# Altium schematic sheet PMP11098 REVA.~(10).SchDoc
size 431 x 279 mm; Date: Not shown in title block; ApprovedBy: Not shown in title block; CheckedBy: Not shown in title block; Author: Not shown in title block; CompanyName: Not shown in title block; Engineer: Not shown in title block; Organization: Not shown in title block; Address1: Not shown in title block; Address2: Not shown in title block; Address3: Not shown in title block; Address4: Not shown in title block; DocumentNumber: 1; Revision: Use project parameter SCH_Rev; SheetNumber: 1; SheetTotal: 1; PageSetup: Record=PageOptions¦CenterHorizontal=True¦CenterVertical=True¦PrintScale=1.00¦XCorrection=1.00¦YCorrection=1.00¦PrintKind=0¦BorderSize=5000000¦LeftOffset=0¦BottomOffset=0¦Orientation=2¦PaperLength=1000¦PaperWidth=1000¦Scale=100¦PaperSource=15¦PrintQuality=600¦MediaType=1¦DitherType=10¦PaperKind=Letter¦PrintScaleMode=1
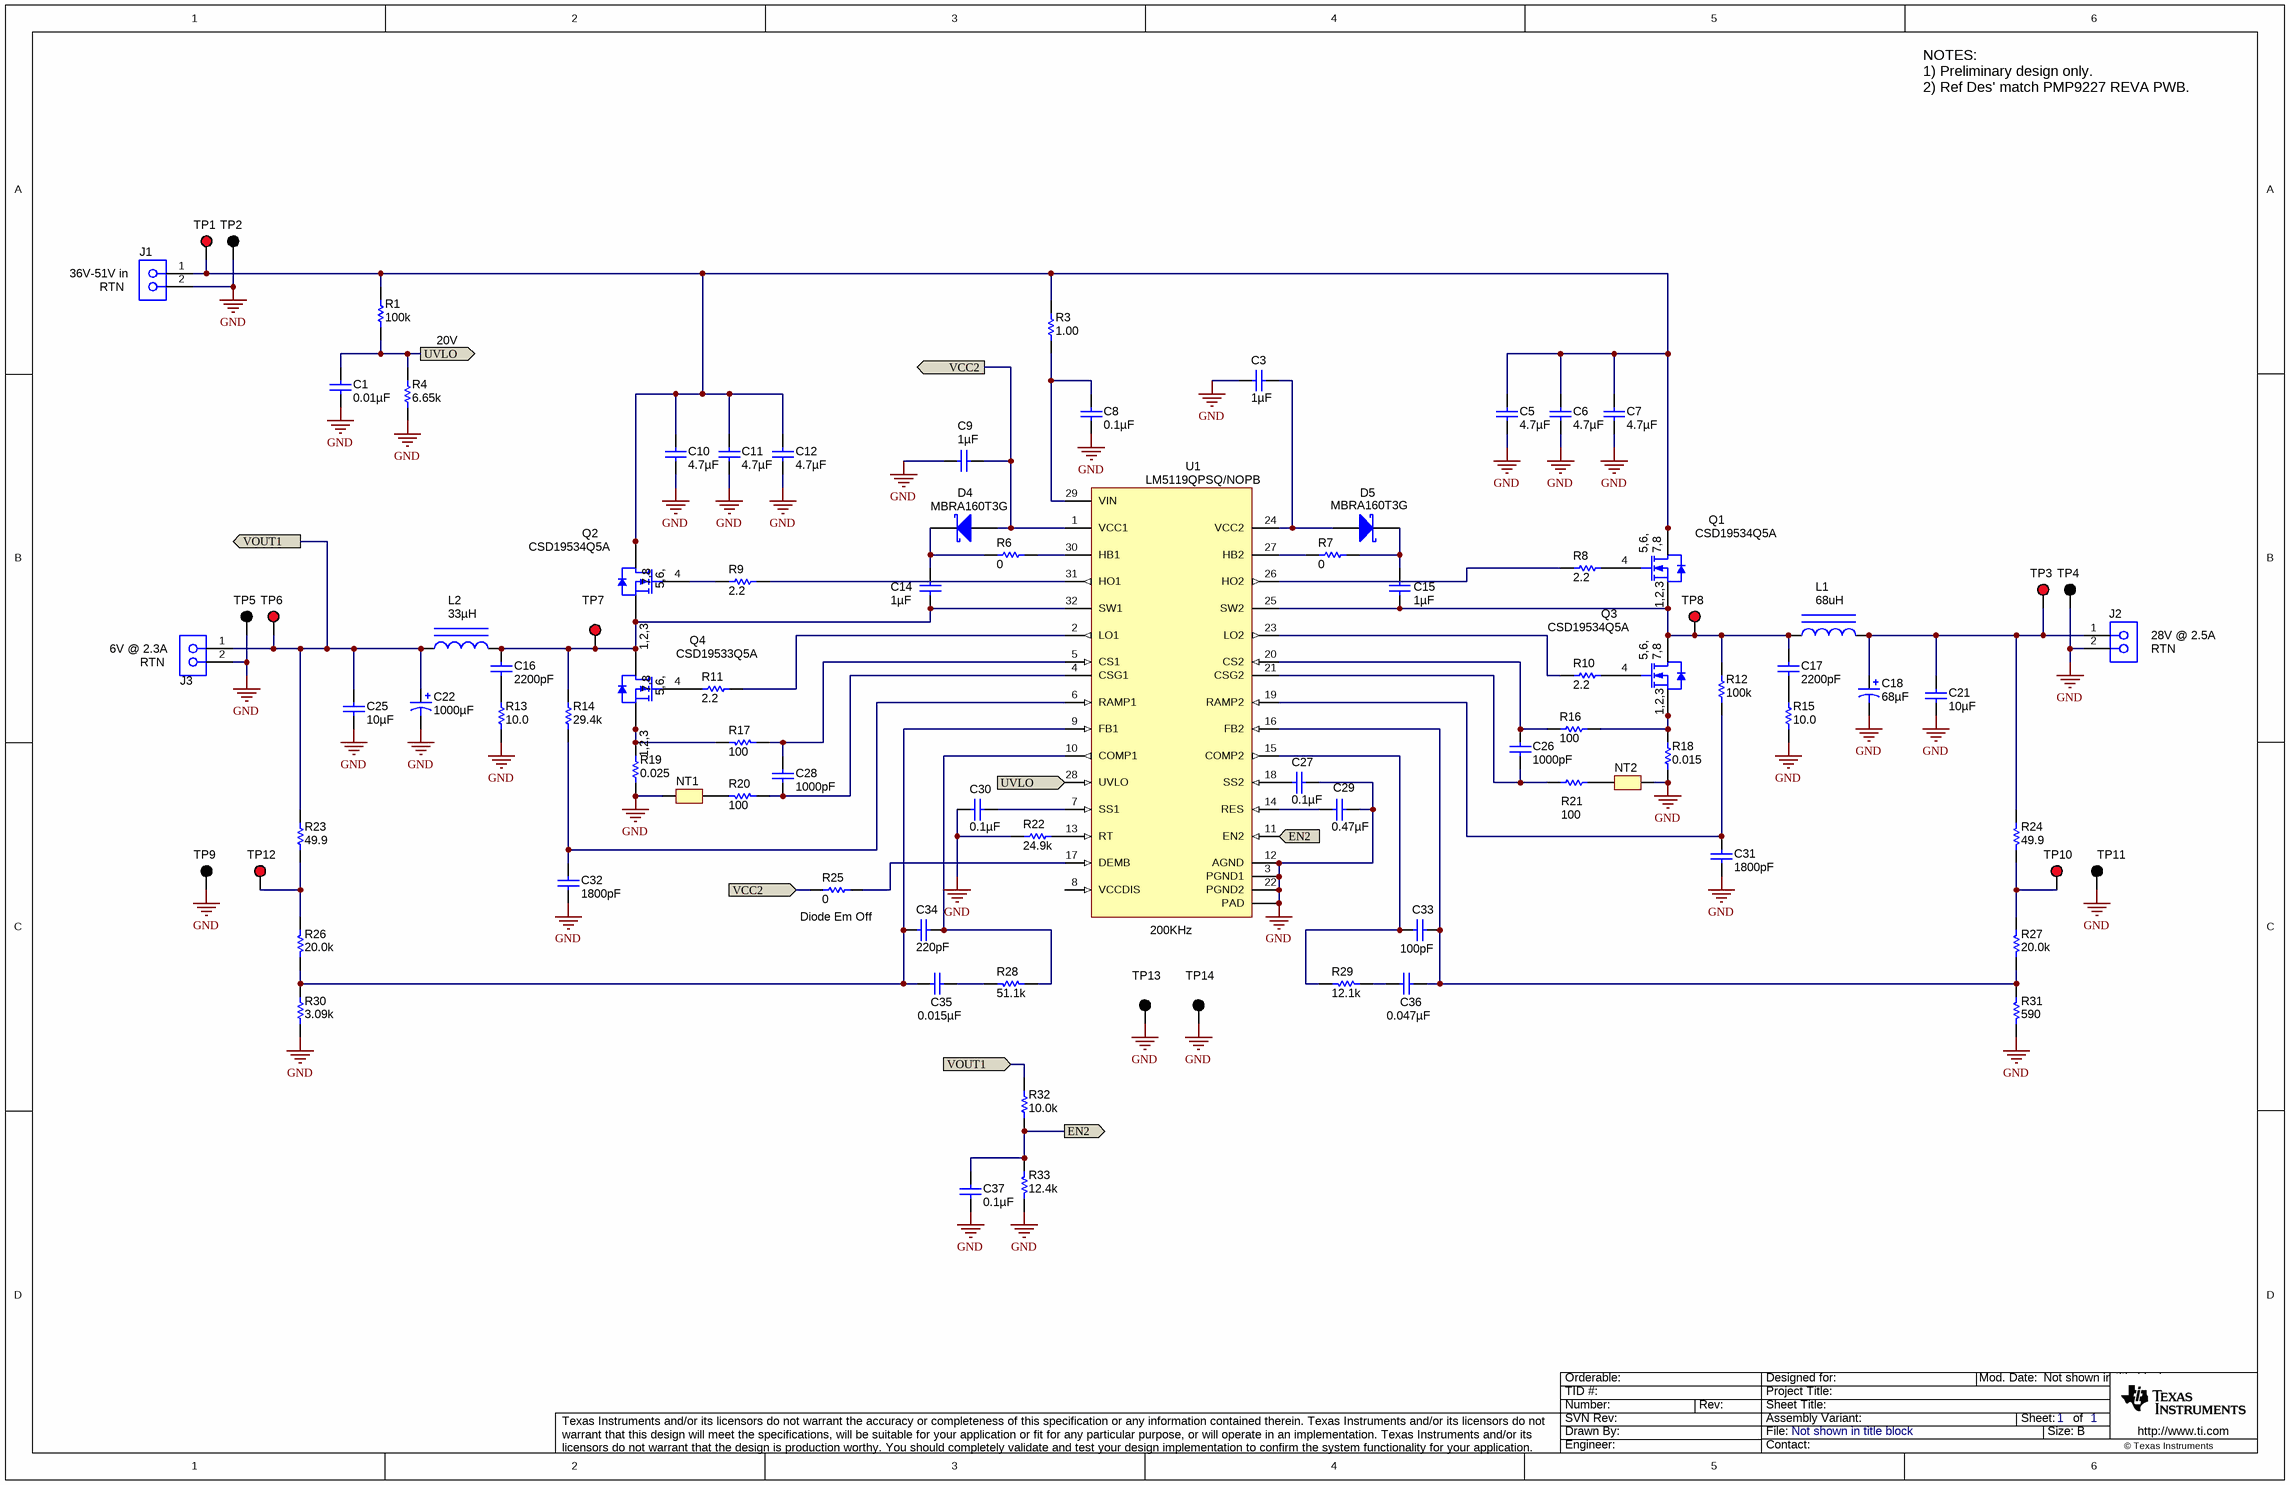
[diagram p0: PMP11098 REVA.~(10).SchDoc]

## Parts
C1  ValueDisplayed: 0.01µF  [0603L]  (hidden comment: C1608X7R1H103K)
C3  ValueDisplayed: 1µF  [0603L]  (hidden comment: C1608X7R1E105K080AB)
C5  ValueDisplayed: 4.7µF  [1210L]  (hidden comment: C3225X7S2A475M200AB)
C6  ValueDisplayed: 4.7µF  [1210L]  (hidden comment: C3225X7S2A475M200AB)
C7  ValueDisplayed: 4.7µF  [1210L]  (hidden comment: C3225X7S2A475M200AB)
C8  ValueDisplayed: 0.1µF  [0603L]  (hidden comment: 06035C104KAT2A)
C9  ValueDisplayed: 1µF  [0603L]  (hidden comment: C1608X7R1E105K080AB)
C10  ValueDisplayed: 4.7µF  [1210L]  (hidden comment: C3225X7S2A475M200AB)
C11  ValueDisplayed: 4.7µF  [1210L]  (hidden comment: C3225X7S2A475M200AB)
C12  ValueDisplayed: 4.7µF  [1210L]  (hidden comment: C3225X7S2A475M200AB)
C14  ValueDisplayed: 1µF  [0603L]  (hidden comment: C1608X7R1E105K080AB)
C15  ValueDisplayed: 1µF  [0603L]  (hidden comment: C1608X7R1E105K080AB)
C16  ValueDisplayed: 2200pF  [0603L]  (hidden comment: C0603C222K5RAC)
C17  ValueDisplayed: 2200pF  [0603L]  (hidden comment: C0603C222K5RAC)
C18  ValueDisplayed: 68µF  [SM_RADIAL_10AMM]  (hidden comment: 50SVPF68M)
C21  ValueDisplayed: 10µF  [1210L]  (hidden comment: GMK325AB7106MM-T)
C22  ValueDisplayed: 1000µF  [SM_RADIAL_10AMM]  (hidden comment: 16SVPF1000M)
C25  ValueDisplayed: 10µF  [1210L]  (hidden comment: GMK325AB7106MM-T)
C26  ValueDisplayed: 1000pF  [0603L]  (hidden comment: 06031C102KAT2A)
C27  ValueDisplayed: 0.1µF  [0603L]  (hidden comment: C1608X7R1H104K)
C28  ValueDisplayed: 1000pF  [0603L]  (hidden comment: 06031C102KAT2A)
C29  ValueDisplayed: 0.47µF  [0603L]  (hidden comment: C0603C474K4RACTU)
C30  ValueDisplayed: 0.1µF  [0603L]  (hidden comment: C1608X7R1H104K)
C31  ValueDisplayed: 1800pF  [0603L]  (hidden comment: C1608C0G1H182J)
C32  ValueDisplayed: 1800pF  [0603L]  (hidden comment: C1608C0G1H182J)
C33  ValueDisplayed: 100pF  [0603]  (hidden comment: C1608C0G1H101J)
C34  ValueDisplayed: 220pF  [0603]  (hidden comment: C1608C0G1H221J)
C35  ValueDisplayed: 0.015µF  [0603L]  (hidden comment: C1608X7R1H153K)
C36  ValueDisplayed: 0.047µF  [0603]  (hidden comment: C1608X7R1H473K)
C37  ValueDisplayed: 0.1µF  [0603L]  (hidden comment: C1608X7R1H104K)
D4  MBRA160T3G  [SMA]
D5  MBRA160T3G  [SMA]
J1  ED120/2DS  [CONN_ED120-2DS]  (value not drawn)
J2  ED120/2DS  [CONN_ED120-2DS]  (value not drawn)
J3  ED120/2DS  [CONN_ED120-2DS]  (value not drawn)
L1  value 68uH  [MSS1210]  (hidden comment: MSS1210-683ME)
L2  ValueDisplayed: 33µH  [MSS1210]  (hidden comment: MSS1210-333ME)
NT1  Net-Tie  [Net-Tie_10mil]  (value not drawn)  (net tie, no BOM)
NT2  Net-Tie  [Net-Tie_10mil]  (value not drawn)  (net tie, no BOM)
Q1  CSD19534Q5A  [TRANS_NexFET_Q5A]
Q2  CSD19534Q5A  [TRANS_NexFET_Q5A]
Q3  CSD19534Q5A  [TRANS_NexFET_Q5A]
Q4  CSD19533Q5A  [TRANS_NexFET_Q5A]
R1  value 100k  [0603L]  (hidden comment: CRCW0603100KFKEA)
R3  value 1.00  [0603L]  (hidden comment: CRCW06031R00FKEA)
R4  value 6.65k  [0603L]  (hidden comment: CRCW06036K65FKEA)
R6  value 0  [0603L]  (hidden comment: CRCW06030000Z0EA)
R7  value 0  [0603L]  (hidden comment: CRCW06030000Z0EA)
R8  value 2.2  [0603L]  (hidden comment: CRCW06032R20JNEA)
R9  value 2.2  [0603L]  (hidden comment: CRCW06032R20JNEA)
R10  value 2.2  [0603L]  (hidden comment: CRCW06032R20JNEA)
R11  value 2.2  [0603L]  (hidden comment: CRCW06032R20JNEA)
R12  ValueDisplayed: 100k  [0603]  (hidden comment: CRCW0603100KFKEA)
R13  value 10.0  [1206L]  (hidden comment: CRCW120610R0FKEA)
R14  ValueDisplayed: 29.4k  [0603]  (hidden comment: CRCW060329K4FKEA)
R15  value 10.0  [1206L]  (hidden comment: CRCW120610R0FKEA)
R16  value 100  [0603L]  (hidden comment: RC0603FR-07100RL)
R17  value 100  [0603L]  (hidden comment: RC0603FR-07100RL)
R18  value 0.015  [1206]  (hidden comment: CSR1206FK15L0)
R19  ValueDisplayed: 0.025  [2010]  (hidden comment: CSRN2010FK25L0)
R20  value 100  [0603L]  (hidden comment: RC0603FR-07100RL)
R21  value 100  [0603L]  (hidden comment: RC0603FR-07100RL)
R22  ValueDisplayed: 24.9k  [0603L]  (hidden comment: CRCW060324K9FKEA)
R23  value 49.9  [0603L]  (hidden comment: CRCW060349R9FKEA)
R24  value 49.9  [0603L]  (hidden comment: CRCW060349R9FKEA)
R25  value 0  [0603L]  (hidden comment: CRCW06030000Z0EA)
R26  value 20.0k  [0603L]  (hidden comment: CRCW060320K0FKEA)
R27  value 20.0k  [0603L]  (hidden comment: CRCW060320K0FKEA)
R28  value 51.1k  [0603]  (hidden comment: CRCW060351K1FKEA)
R29  ValueDisplayed: 12.1k  [0603]  (hidden comment: CRCW060312K1FKEA)
R30  ValueDisplayed: 3.09k  [0603L]  (hidden comment: CRCW06033K09FKEA)
R31  ValueDisplayed: 590  [0603]  (hidden comment: CRCW0603590RFKEA)
R32  value 10.0k  [0603L]  (hidden comment: CRCW060310K0FKEA)
R33  value 12.4k  [0603]  (hidden comment: CRCW060312K4FKEA)
TP1  5010  [Keystone5010]  (value not drawn)
TP2  5011  [Keystone5011]  (value not drawn)
TP3  5010  [Keystone5010]  (value not drawn)
TP4  5011  [Keystone5011]  (value not drawn)
TP5  5011  [Keystone5011]  (value not drawn)
TP6  5010  [Keystone5010]  (value not drawn)
TP7  5010  [Keystone5010]  (value not drawn)
TP8  5010  [Keystone5010]  (value not drawn)
TP9  5011  [Keystone5011]  (value not drawn)
TP10  5010  [Keystone5010]  (value not drawn)
TP11  5011  [Keystone5011]  (value not drawn)
TP12  5010  [Keystone5010]  (value not drawn)
TP13  5011  [Keystone5011]  (value not drawn)
TP14  5011  [Keystone5011]  (value not drawn)
U1  LM5119QPSQ/NOPB  [RTV0032A]

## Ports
EN2, UVLO, VCC2, VOUT1

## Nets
GND: C1.2 C3.2 C5.2 C6.2 C7.2 C8.2 C9.2 C10.2 C11.2 C12.2 C18.2(-) C21.2 C22.2(-) C25.2 C27.1 C29.1 C30.2 C31.2 C32.2 C37.2 J1.2 J2.2 J3.2 NT1.1 NT2.2 R4.1 R13.1 R15.1 R18.1 R19.1 R22.1 R30.1 R31.1 R33.1 TP2.1 TP4.1 TP5.1 TP9.1 TP11.1 TP13.1 TP14.1 U1.3(PGND1) U1.12(AGND) U1.22(PGND2) U1.33(PAD)
EN2: C37.1 R32.1 R33.2 U1.11(EN2) ; port EN2
UVLO: C1.1 R1.1 R4.2 U1.28(UVLO) ; port UVLO
VCC2: C9.1 D4.2(A) R25.1 U1.1(VCC1) ; port VCC2
VOUT1: C22.1(+) C25.1 J3.1 L2.1 R23.2 R32.2 TP6.1 ; port VOUT1
NetC3_1: C3.1 D5.2(A) U1.24(VCC2)
NetC5_1: C5.1 C6.1 C7.1 C10.1 C11.1 C12.1 J1.1 Q1.5(D) Q1.6(D) Q1.7(D) Q1.8(D) Q1.9(D) Q2.5(D) Q2.6(D) Q2.7(D) Q2.8(D) Q2.9(D) R1.2 R3.2 TP1.1
NetC8_1: C8.1 R3.1 U1.29(VIN)
NetC14_1: C14.1 D4.1(K) R6.1
NetC14_2: C14.2 C16.1 L2.2 Q2.1(S) Q2.2(S) Q2.3(S) Q4.5(D) Q4.6(D) Q4.7(D) Q4.8(D) Q4.9(D) R14.2 TP7.1 U1.32(SW1)
NetC15_1: C15.1 D5.1(K) R7.2
NetC15_2: C15.2 C17.1 L1.1 Q1.1(S) Q1.2(S) Q1.3(S) Q3.5(D) Q3.6(D) Q3.7(D) Q3.8(D) Q3.9(D) R12.2 TP8.1 U1.25(SW2)
NetC16_2: C16.2 R13.2
NetC17_2: C17.2 R15.2
NetC18_1: C18.1(+) C21.1 J2.1 L1.2 R24.2 TP3.1
NetC26_1: C26.1 R21.1 U1.21(CSG2)
NetC26_2: C26.2 R16.1 U1.20(CS2)
NetC27_2: C27.2 U1.18(SS2)
NetC28_1: C28.1 R17.1 U1.5(CS1)
NetC28_2: C28.2 R20.1 U1.4(CSG1)
NetC29_2: C29.2 U1.14(RES)
NetC30_1: C30.1 U1.7(SS1)
NetC31_1: C31.1 R12.1 U1.19(RAMP2)
NetC32_1: C32.1 R14.1 U1.6(RAMP1)
NetC33_1: C33.1 C36.1 R27.1 R31.2 U1.16(FB2)
NetC33_2: C33.2 R29.2 U1.15(COMP2)
NetC34_1: C34.1 R28.1 U1.10(COMP1)
NetC34_2: C34.2 C35.2 R26.1 R30.2 U1.9(FB1)
NetC35_1: C35.1 R28.2
NetC36_2: C36.2 R29.1
NetNT1_2: NT1.2 R20.2
NetNT2_1: NT2.1 R21.2
NetQ1_4: Q1.4(G) R8.2
NetQ2_4: Q2.4(G) R9.1
NetQ3_1: Q3.1(S) Q3.2(S) Q3.3(S) R16.2 R18.2
NetQ3_4: Q3.4(G) R10.2
NetQ4_1: Q4.1(S) Q4.2(S) Q4.3(S) R17.2 R19.2
NetQ4_4: Q4.4(G) R11.1
NetR6_2: R6.2 U1.30(HB1)
NetR7_1: R7.1 U1.27(HB2)
NetR8_1: R8.1 U1.26(HO2)
NetR9_2: R9.2 U1.31(HO1)
NetR10_1: R10.1 U1.23(LO2)
NetR11_2: R11.2 U1.2(LO1)
NetR22_2: R22.2 U1.13(RT)
NetR23_1: R23.1 R26.2 TP12.1
NetR24_1: R24.1 R27.2 TP10.1
NetR25_2: R25.2 U1.17(DEMB)

Not connected (* = marked no-connect by the designer): U1 8(VCCDIS)

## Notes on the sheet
- NOTES:
  1) Preliminary design only.
  2) Ref Des' match PMP9227 REVA PWB.
- (near J1) 36V-51V in
- (near J1) RTN
- 20V
- (near J2) 28V @ 2.5A
- (near J3) 6V @ 2.3A
- (near J3) RTN
- (near J2) RTN
- (near R25) Diode Em Off
- (near U1) 200KHz

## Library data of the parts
C1 = C1608X7R1H103K: CAP, CERM, 0.01uF, 50V, +/-10%, X7R, 0603; Manufacturer: TDK; Polarized: N; CompType: Capacitor; U/M: EA; Cap_F: 0.00000001; Tolerance_%: 10; ESR_Ohm: 0.0539; Value1: 0.0539 ohm; VDC_V: 50; TaMin_C: -55; TaMax_C: 125; Cap_Case: 0603
C3 C9 C14 C15 = C1608X7R1E105K080AB: CAP, CERM, 1uF, 25V, +/-10%, X7R, 0603; Manufacturer: TDK; Polarized: N; CompType: Capacitor; U/M: EA; Cap_F: 0.000001; Tolerance_%: 10; Value1: Unknown; VDC_V: 25; TaMin_C: -55; TaMax_C: 125; Cap_Case: 0603
C5-C7 C10-C12 = C3225X7R1H335M: CAP, CERM, 4.7uF, 100V, +/-20%, X7S, 1210; Manufacturer: TDK; Polarized: N; CompType: Capacitor; U/M: EA; Cap_F: 0.0000033; Tolerance_%: 20; Value1: Unknown; VDC_V: 100; TempCo: X7R; TaMin_C: -55; TaMax_C: 125; Cap_Case: 1210
C8 = 06035C104KAT2A: CAP, CERM, 0.1uF, 50V, +/-10%, X7R, 0603; Manufacturer: AVX; Polarized: N; CompType: Capacitor; U/M: EA; Cap_F: 0.0000001; Tolerance_%: 10; Value1: Unknown; VDC_V: 50; TaMin_C: -55; TaMax_C: 125; Cap_Case: 0603
C16 C17 = C0603C222K5RAC: CAP, CERM, 2200pF, 50V, +/-10%, X7R, 0603; Manufacturer: Kemet; Polarized: N; CompType: Capacitor; U/M: EA; Cap_F: 0.0000000022; Tolerance_%: 10; Value1: Unknown; VDC_V: 50; TaMin_C: -55; TaMax_C: 125; Cap_Case: 0603
C18 = 10SVP270M: CAP, OS-CON, 68uF, 50V, +/-20%, 0.020 ohm, F12, SMD; Manufacturer: Sanyo; Polarized: Y; CompType: Capacitor; U/M: EA; Cap_F: 0.00027; Tolerance_%: 20; VDC_V: 50; ESR_Ohm: 0.025; IRMS_A: 3.7; TaMin_C: -55; TaMax_C: 105; Cap_Case: 10.3x10.3x7.9
C21 C25 = GMK325AB7106MM-T: CAP, CERM, 10uF, 35V, +/-20%, X7R, 1210; Manufacturer: Taiyo Yuden; Polarized: N; CompType: Capacitor; U/M: EA; Cap_F: 0.00001; Tolerance_%: 20; Value1: Unknown; VDC_V: 35; TaMin_C: -55; TaMax_C: 125; Cap_Case: 1210
C22 = 10SVP270M: CAP, OS-CON, 1000uF, 16V, +/-20%, 0.012 ohm, F12, SMD; Manufacturer: Sanyo; Polarized: Y; CompType: Capacitor; U/M: EA; Cap_F: 0.00027; Tolerance_%: 20; VDC_V: 16; ESR_Ohm: 0.025; IRMS_A: 3.7; TaMin_C: -55; TaMax_C: 105; Cap_Case: 10.3x10.3x7.9
C26 C28 = 06031C102KAT2A: CAP, CERM, 1000pF, 100V, +/-10%, X7R, 0603; Manufacturer: AVX; Polarized: N; CompType: Capacitor; U/M: EA; Cap_F: 0.000000001; Tolerance_%: 10; ESR_Ohm: 0.276; Value1: 0.276 ohm; VDC_V: 100; TaMin_C: -55; TaMax_C: 125; Cap_Case: 0603
C27 C30 C37 = C1608X7R1H104K: CAP, CERM, 0.1uF, 50V, +/-10%, X7R, 0603; Manufacturer: TDK; Polarized: N; CompType: Capacitor; U/M: EA; Cap_F: 0.0000001; Tolerance_%: 10; ESR_Ohm: 0.017; Value1: 0.017 ohm; VDC_V: 50; TaMin_C: -55; TaMax_C: 125; Cap_Case: 0603
C29 = C0603C474K4RACTU: CAP, CERM, 0.47uF, 16V, +/-10%, X7R, 0603; Manufacturer: Kemet; Polarized: N; CompType: Capacitor; U/M: EA; Cap_F: 0.00000047; Tolerance_%: 10; Value1: Unknown; VDC_V: 16; TaMin_C: -55; TaMax_C: 125; Cap_Case: 0603
C31 C32 = C1608C0G1H182J: CAP, CERM, 1800pF, 50V, +/-5%, C0G/NP0, 0603; Manufacturer: TDK; Polarized: N; CompType: Capacitor; U/M: EA; Cap_F: 0.0000000018; Tolerance_%: 5; Value1: Unknown; VDC_V: 50; TaMin_C: -55; TaMax_C: 125; Cap_Case: 0603
C33 = C1608C0G1H101J: CAP, CERM, 100pF, 50V, +/-5%, C0G/NP0, 0603; Manufacturer: TDK; Polarized: N; CompType: Capacitor; U/M: EA; Cap_F: 0.0000000001; Tolerance_%: 5; ESR_Ohm: 0.1679; Value1: 0.1679 ohm; VDC_V: 50; TaMin_C: -55; TaMax_C: 125
C34 = C1608C0G1H221J: CAP, CERM, 220pF, 50V, +/-5%, C0G/NP0, 0603; Manufacturer: TDK; Polarized: N; CompType: Capacitor; U/M: EA; Cap_F: 0.00000000022; Tolerance_%: 5; ESR_Ohm: 0.0831; Value1: 0.0831 ohm; VDC_V: 50; TaMin_C: -55; TaMax_C: 125
C35 = C1608X7R1H473K: CAP, CERM, 0.015uF, 50V, +/-10%, X7R, 0603; Manufacturer: TDK; Polarized: N; CompType: Capacitor; U/M: EA; Cap_F: 0.000000047; Tolerance_%: 10; ESR_Ohm: 0.0234; Value1: 0.0234 ohm; VDC_V: 50; TaMin_C: -55; TaMax_C: 125; Cap_Case: 0603
C36 = C1608X7R1H473K: CAP, CERM, 0.047uF, 50V, +/-10%, X7R, 0603; Manufacturer: TDK; Polarized: N; CompType: Capacitor; U/M: EA; Cap_F: 0.000000047; Tolerance_%: 10; ESR_Ohm: 0.0234; Value1: 0.0234 ohm; VDC_V: 50; TaMin_C: -55; TaMax_C: 125
D4 D5 = MBRA160T3G: Diode, Schottky, 60V, 1A, SMA; Manufacturer: ON Semiconductor; Value: 0.51V; U/M: EA; Vf_V: 0.51; Io_A: 1; Vr_V: 60; TJmax_C: 150; RJC_CperW: 35
J1-J3 = ED120/2DS: TERMINAL BLOCK 5.08MM VERT 2POS; Manufacturer: On-Shore Technology, Inc.; U/M: EA
L1 = MSS1210-683ME: Inductor, Shielded, Ferrite, 68 µH, 4.3 A, 0.074 ohm, SMD; Manufacturer: Coilcraft; Ind_H: 68.0E-6; ValueDisplayed: 68µH; Imax_A: 4.3; Irms: 4.3A @ 40C rise; Isat: 4.9A @ 30% inductance drop; DCR_ohm: 0.074; Value2: 4.3A
L2 = MSS1210-333ME: Inductor, Shielded, Ferrite, 33 µH, 5.9 A, 0.034 ohm, SMD; Manufacturer: Coilcraft; Value: 33uH; Ind_H: 33.0E-6; Imax_A: 5.9; Irms: 5.9A @ 40C rise; Isat: 6.9A @ 30% inductance drop; DCR_ohm: 0.034; Value2: 5.9A
NT1 NT2 = Net-Tie: Single point connection between nets.; SymbolCreator: codlsc
Q1-Q3 = CSD19531Q5A: MOSFET, N-CH, 100V, 15nC, 0.0124 ohm, SON 5x6mm; Manufacturer: Texas Instruments; Alternate Manufacturer: None; U/M: EA; ChType: N; VdsMax_V: 100; QgTyp_nC: 26; Vgs_V: 20; IdsMax_A: 16
Q4 = CSD19533Q5A: MOSFET, N-CH, 100V, 13A, SON 5x6mm; Manufacturer: Texas Instruments; Alternate Manufacturer: None; U/M: EA; ChType: N; VdsMax_V: 100; Value1: ? ohm; Value2: 27 nC; QgTyp_nC: 27; Vgs_V: 20; IdsMax_A: 13
R1 = CRCW0603100KFKEA: RES, 100k ohm, 1%, 0.1W, 0603; Manufacturer: Vishay-Dale; CompType: Resistor; Res_ohm: 100000; Tolerance_%: 1; Power_W: 0.1; VDC_V: 75; TempCo: 100 ppm/C; EIA_Code: E96; U/M: EA
R3 = CRCW06031R00FKEA: RES, 1.00 ohm, 1%, 0.1W, 0603; Manufacturer: Vishay-Dale; CompType: Resistor; Res_ohm: 1; Value_Code: 1R00; Power_W: 0.1; VDC_V: 75; TempCo: 100 ppm/C; EIA_Code: E96; U/M: EA
R4 = CRCW06036K65FKEA: RES, 6.65k ohm, 1%, 0.1W, 0603; Manufacturer: Vishay-Dale; CompType: Resistor; Res_ohm: 6650; Value_Code: 6k65; Tolerance_%: 1; Power_W: 0.1; VDC_V: 75; TempCo: 100 ppm/C; EIA_Code: E96; U/M: EA
R6 R7 R25 = CRCW06030000Z0EA: RES, 0 ohm, 5%, 0.1W, 0603; Manufacturer: Vishay-Dale; CompType: Resistor; Value_Code: 0000; Tolerance_%: 5; Power_W: 0.1; VDC_V: 75; TempCo: 200 ppm/C; EIA_Code: E24; U/M: EA
R8-R11 = CRCW06032R20JNEA: RES, 2.2 ohm, 5%, 0.1W, 0603; Manufacturer: Vishay-Dale; CompType: Resistor; Value_Code: 2R20; Tolerance_%: 5; Power_W: 0.1; VDC_V: 75; TempCo: 200 ppm/C; EIA_Code: E24; U/M: EA
R12 = CRCW0603100KFKEA: RES, 100 k, 1%, 0.1 W, 0603; Manufacturer: Vishay-Dale; CompType: Resistor; Value: 100k; Res_ohm: 100000; Tolerance_%: 1; Power_W: 0.1; Value2: 0.1W; VDC_V: 75; TempCo: 100 ppm/C; EIA_Code: E96; U/M: EA
R13 R15 = CRCW120610R0FKEA: RES, 10.0 ohm, 1%, 0.25W, 1206; Manufacturer: Vishay-Dale; CompType: Resistor; Res_ohm: 10; Value_Code: 10R0; Tolerance_%: 1; Power_W: 0.25; VDC_V: 200; TempCo: 100 ppm/C; EIA_Code: E96; U/M: EA
R14 = CRCW060329K4FKEA: RES, 29.4 k, 1%, 0.1 W, 0603; Manufacturer: Vishay-Dale; CompType: Resistor; Value: 29.4k; Res_ohm: 29400; Value_Code: 29k4; Tolerance_%: 1; Power_W: 0.1; Value2: 0.1W; VDC_V: 75; TempCo: 100 ppm/C; EIA_Code: E96; U/M: EA
R16 R17 R20 R21 = RC0603FR-07100RL: RES, 100 ohm, 1%, 0.1W, 0603; Manufacturer: Yageo America; CompType: Resistor; Value_Code: 100R; Tolerance_%: 1; Power_W: 0.1; VDC_V: 150; TempCo: 200 ppm/C; EIA_Code: E96; U/M: EA
R18 = CSR1206FK15L0: RES, 0.015 ohm, 1%, 0.5W, 1206; Manufacturer: Stackpole Electronics Inc; CompType: Resistor; Value_Code: R015; Tolerance_%: 1; Power_W: 0.5; TempCo: 100 ppm/C; EIA_Code: E96; U/M: EA
R19 = CSRN2010FK25L0: RES, 0.025, 1%, 1 W, 2010; Manufacturer: Stackpole Electronics Inc; CompType: Resistor; Value: 0.025; Value_Code: R025; Tolerance_%: 1; Value2: 1W; TempCo: 250 ppm/C; EIA_Code: E96; U/M: EA
R22 = CRCW060324K9FKEA: RES, 24.9 k, 1%, 0.1 W, 0603; Manufacturer: Vishay-Dale; CompType: Resistor; Value: 24.9k; Res_ohm: 24900; Value_Code: 24k9; Tolerance_%: 1; Power_W: 0.1; Value2: 0.1W; VDC_V: 75; TempCo: 100 ppm/C; EIA_Code: E96; U/M: EA
R23 R24 = CRCW060349R9FKEA: RES, 49.9 ohm, 1%, 0.1W, 0603; Manufacturer: Vishay-Dale; CompType: Resistor; Value_Code: 49R9; Tolerance_%: 1; Power_W: 0.1; VDC_V: 75; TempCo: 100 ppm/C; EIA_Code: E96; U/M: EA
R26 R27 = CRCW060320K0FKEA: RES, 20.0k ohm, 1%, 0.1W, 0603; Manufacturer: Vishay-Dale; CompType: Resistor; Res_ohm: 20000; Value_Code: 20k0; Tolerance_%: 1; Power_W: 0.1; VDC_V: 75; TempCo: 100 ppm/C; EIA_Code: E96; U/M: EA
R28 = CRCW060351K1FKEA: RES, 51.1k ohm, 1%, 0.1W, 0603; Manufacturer: Vishay-Dale; CompType: Resistor; Res_ohm: 51100; Value_Code: 51k1; Tolerance_%: 1; Power_W: 0.1; VDC_V: 75; TempCo: 100 ppm/C; EIA_Code: E96; U/M: EA
R29 = CRCW060312K1FKEA: RES, 12.1 k, 1%, 0.1 W, 0603; Manufacturer: Vishay-Dale; CompType: Resistor; Value: 12.1k; Res_ohm: 12100; Value_Code: 12k1; Tolerance_%: 1; Power_W: 0.1; Value2: 0.1W; VDC_V: 75; TempCo: 100 ppm/C; EIA_Code: E96; U/M: EA
R30 = CRCW06033K09FKEA: RES, 3.09 k, 1%, 0.1 W, 0603; Manufacturer: Vishay-Dale; CompType: Resistor; Value: 3.09k; Res_ohm: 3090; Value_Code: 3k09; Tolerance_%: 1; Power_W: 0.1; Value2: 0.1W; VDC_V: 75; TempCo: 100 ppm/C; EIA_Code: E96; U/M: EA
R31 = CRCW0603590RFKEA: RES, 590, 1%, 0.1 W, 0603; Manufacturer: Vishay-Dale; CompType: Resistor; Value: 590; Value_Code: 590R; Tolerance_%: 1; Power_W: 0.1; Value2: 0.1W; VDC_V: 75; TempCo: 100 ppm/C; EIA_Code: E96; U/M: EA
R32 = CRCW060310K0FKEA: RES, 10.0k ohm, 1%, 0.1W, 0603; Manufacturer: Vishay-Dale; CompType: Resistor; Res_ohm: 10000; Value_Code: 10k0; Tolerance_%: 1; Power_W: 0.1; VDC_V: 75; TempCo: 100 ppm/C; EIA_Code: E96; U/M: EA
R33 = CRCW060312K4FKEA: RES, 12.4k ohm, 1%, 0.1W, 0603; Manufacturer: Vishay-Dale; CompType: Resistor; Res_ohm: 12400; Value_Code: 12k4; Tolerance_%: 1; Power_W: 0.1; VDC_V: 75; TempCo: 100 ppm/C; EIA_Code: E96; U/M: EA
TP1 TP3 TP6-TP8 TP10 TP12 = 5010: Test Point, Multipurpose, Red, TH; Manufacturer: Keystone; CompType: Test Point Loop; U/M: EA
TP2 TP4 TP5 TP9 TP11 TP13 TP14 = 5011: Test Point, Multipurpose, Black, TH; Manufacturer: Keystone; CompType: Test Point Loop; U/M: EA
U1 = LM5119PSQ/NOPB: LM5119/LM5119Q Wide Input Range Dual Synchronous Buck Controller, RTV0032A; Alternate Manufacturer: None; Manufacturer: Texas Instruments; SymbolCreator: a0411947; CompType: IC; U/M: EA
